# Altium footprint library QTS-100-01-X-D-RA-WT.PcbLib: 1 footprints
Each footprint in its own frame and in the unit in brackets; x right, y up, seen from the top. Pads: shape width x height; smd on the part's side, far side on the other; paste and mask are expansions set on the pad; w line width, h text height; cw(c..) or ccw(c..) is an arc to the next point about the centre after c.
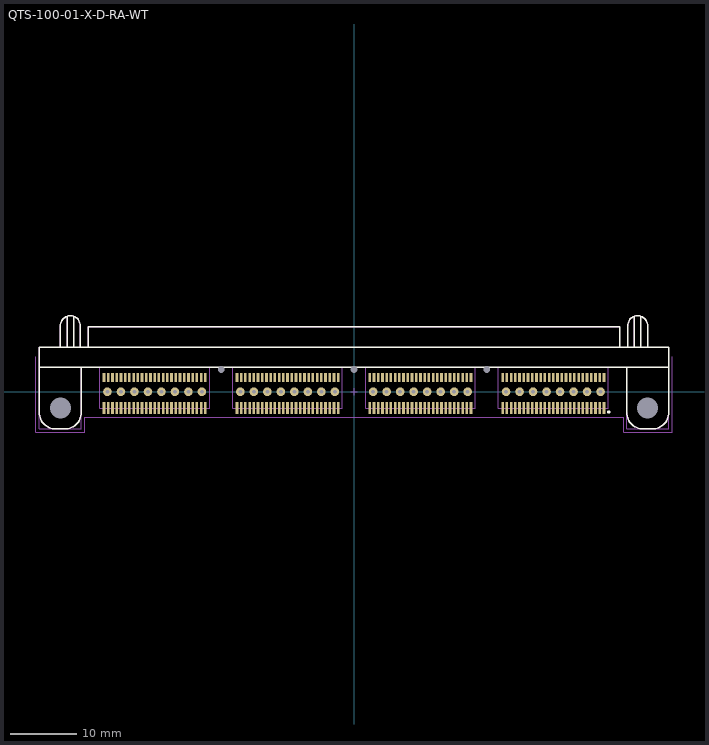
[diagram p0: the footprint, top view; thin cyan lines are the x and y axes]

## QTS-100-01-X-D-RA-WT [mm] "0.635mm pitch, 200 pin, high speed terminal strip; r/a, w/weld tabs"
height 9.42
pads (237):
  rect 0.4x1.8 smd mask+0: 1(37.624,-2.451) 3(36.989,-2.451) 5(36.354,-2.451) 7(35.719,-2.451) 9(35.084,-2.451) 11(34.449,-2.451) 13(33.814,-2.451) 15(33.179,-2.451) 17(32.544,-2.451) 19(31.909,-2.451) 21(31.274,-2.451) 23(30.639,-2.451) 25(30.004,-2.451) 27(29.369,-2.451) 29(28.734,-2.451) 31(28.099,-2.451) 33(27.464,-2.451) 35(26.829,-2.451) 37(26.194,-2.451) 39(25.559,-2.451) 41(24.924,-2.451) 43(24.289,-2.451) 45(23.654,-2.451) 47(23.019,-2.451) 49(22.384,-2.451) 51(17.621,-2.451) 53(16.986,-2.451) 55(16.351,-2.451) 57(15.716,-2.451) 59(15.081,-2.451) 61(14.446,-2.451) 63(13.811,-2.451) 65(13.176,-2.451) 67(12.541,-2.451) 69(11.906,-2.451) 71(11.271,-2.451) 73(10.636,-2.451) 75(10.001,-2.451) 77(9.366,-2.451) 79(8.731,-2.451) 81(8.096,-2.451) 83(7.461,-2.451) 85(6.826,-2.451) 87(6.191,-2.451) 89(5.556,-2.451) 91(4.921,-2.451) 93(4.286,-2.451) 95(3.651,-2.451) 97(3.016,-2.451) 99(2.381,-2.451) 101(-2.381,-2.451) 103(-3.016,-2.451) 105(-3.651,-2.451) 107(-4.286,-2.451) 109(-4.921,-2.451) 111(-5.556,-2.451) 113(-6.191,-2.451) 115(-6.826,-2.451) 117(-7.461,-2.451) 119(-8.096,-2.451) 121(-8.731,-2.451) 123(-9.366,-2.451) 125(-10.001,-2.451) 127(-10.636,-2.451) 129(-11.271,-2.451) 131(-11.906,-2.451) 133(-12.541,-2.451) 135(-13.176,-2.451) 137(-13.811,-2.451) 139(-14.446,-2.451) 141(-15.081,-2.451) 143(-15.716,-2.451) 145(-16.351,-2.451) 147(-16.986,-2.451) 149(-17.621,-2.451) 151(-22.384,-2.451) 153(-23.019,-2.451) 155(-23.654,-2.451) 157(-24.289,-2.451) 159(-24.924,-2.451) 161(-25.559,-2.451) 163(-26.194,-2.451) 165(-26.829,-2.451) 167(-27.464,-2.451) 169(-28.099,-2.451) 171(-28.734,-2.451) 173(-29.369,-2.451) 175(-30.004,-2.451) 177(-30.639,-2.451) 179(-31.274,-2.451) 181(-31.909,-2.451) 183(-32.544,-2.451) 185(-33.179,-2.451) 187(-33.814,-2.451) 189(-34.449,-2.451) 191(-35.084,-2.451) 193(-35.719,-2.451) 195(-36.354,-2.451) 197(-36.989,-2.451) 199(-37.624,-2.451)
  rect 0.4x1.4 smd mask+0: 2(37.624,2.159) 4(36.989,2.159) 6(36.354,2.159) 8(35.719,2.159) 10(35.084,2.159) 12(34.449,2.159) 14(33.814,2.159) 16(33.179,2.159) 18(32.544,2.159) 20(31.909,2.159) 22(31.274,2.159) 24(30.639,2.159) 26(30.004,2.159) 28(29.369,2.159) 30(28.734,2.159) 32(28.099,2.159) 34(27.464,2.159) 36(26.829,2.159) 38(26.194,2.159) 40(25.559,2.159) 42(24.924,2.159) 44(24.289,2.159) 46(23.654,2.159) 48(23.019,2.159) 50(22.384,2.159) 52(17.621,2.159) 54(16.986,2.159) 56(16.351,2.159) 58(15.716,2.159) 60(15.081,2.159) 62(14.446,2.159) 64(13.811,2.159) 66(13.176,2.159) 68(12.541,2.159) 70(11.906,2.159) 72(11.271,2.159) 74(10.636,2.159) 76(10.001,2.159) 78(9.366,2.159) 80(8.731,2.159) 82(8.096,2.159) 84(7.461,2.159) 86(6.826,2.159) 88(6.191,2.159) 90(5.556,2.159) 92(4.921,2.159) 94(4.286,2.159) 96(3.651,2.159) 98(3.016,2.159) 100(2.381,2.159) 102(-2.381,2.159) 104(-3.016,2.159) 106(-3.651,2.159) 108(-4.286,2.159) 110(-4.921,2.159) 112(-5.556,2.159) 114(-6.191,2.159) 116(-6.826,2.159) 118(-7.461,2.159) 120(-8.096,2.159) 122(-8.731,2.159) 124(-9.366,2.159) 126(-10.001,2.159) 128(-10.636,2.159) 130(-11.271,2.159) 132(-11.906,2.159) 134(-12.541,2.159) 136(-13.176,2.159) 138(-13.811,2.159) 140(-14.446,2.159) 142(-15.081,2.159) 144(-15.716,2.159) 146(-16.351,2.159) 148(-16.986,2.159) 150(-17.621,2.159) 152(-22.384,2.159) 154(-23.019,2.159) 156(-23.654,2.159) 158(-24.289,2.159) 160(-24.924,2.159) 162(-25.559,2.159) 164(-26.194,2.159) 166(-26.829,2.159) 168(-27.464,2.159) 170(-28.099,2.159) 172(-28.734,2.159) 174(-29.369,2.159) 176(-30.004,2.159) 178(-30.639,2.159) 180(-31.274,2.159) 182(-31.909,2.159) 184(-32.544,2.159) 186(-33.179,2.159) 188(-33.814,2.159) 190(-34.449,2.159) 192(-35.084,2.159) 194(-35.719,2.159) 196(-36.354,2.159) 198(-36.989,2.159) 200(-37.624,2.159)
  round 1.3 hole 0.6 mask+0: 201(37.116,0) 202(35.084,0) 203(33.052,0) 204(31.02,0) 205(28.988,0) 206(26.956,0) 207(24.924,0) 208(22.892,0) 209(17.113,0) 210(15.081,0) 211(13.049,0) 212(11.017,0) 213(8.985,0) 214(6.953,0) 215(4.921,0) 216(2.889,0) 217(-2.89,0) 218(-4.922,0) 219(-6.954,0) 220(-8.986,0) 221(-11.018,0) 222(-13.05,0) 223(-15.082,0) 224(-17.114,0) 225(-22.894,0) 226(-24.926,0) 227(-26.958,0) 228(-28.99,0) 229(-31.022,0) 230(-33.054,0) 231(-35.086,0) 232(-37.118,0)
  round 1 hole 3.2 unplated mask+0: 233(44.196,-2.451) 234(-44.196,-2.451)
  round 0.5 hole 1 unplated mask+0: 235(20.003,3.353) 236(0,3.353) 237(-20.003,3.353)
Top Overlay:
  circle w0.25: c38.35,-3.05 r0.125
  lines w0.2: -47.4,3.693 -47.4,-3.126 ccw(c-44.9,-3.1) -44.869,-5.6 ; -44.87,-5.6 -43.52,-5.6 ; -44.2,6.7 -44.2,9.943 cw(c-42.7,9.943) -41.2,9.943 -41.2,6.7 ; -43.519,-5.6 ccw(c-43.55,-3.1) -41.05,-3.126 ; -43.2,6.7 -43.2,11.35 ; -42.2,6.7 -42.2,11.35 ; -41.05,-3.126 -41.05,3.7 ; -40,6.7 -40,9.75 40,9.75 40,6.693 ; 41.05,-3.126 ccw(c43.55,-3.1) 43.519,-5.6 ; 41.05,-3.126 41.05,3.693 ; 41.2,6.7 41.2,9.943 cw(c42.7,9.943) 44.2,9.943 44.2,6.7 ; 42.2,6.7 42.2,11.35 ; 43.2,6.7 43.2,11.35 ; 43.52,-5.6 44.87,-5.6 ; 44.869,-5.6 ccw(c44.9,-3.1) 47.4,-3.126 47.4,3.7 ; 47.4,3.7 47.4,6.7 -47.4,6.7 -47.4,3.7 47.4,3.7
Mechanical 12:
  lines w0.001: -47.4,-5.6 -47.4,6.7 -40,6.7 -40,9.75 40,9.75 40,6.7 47.4,6.7 47.4,-5.6 41.05,-5.6 41.05,3.7 38.25,3.7 38.25,-2.5 21.75,-2.5 21.75,3.7 18.25,3.7 18.25,-2.5 1.75,-2.5 1.75,3.7 -1.75,3.7 -1.75,-2.5 -18.25,-2.5 -18.25,3.7 -21.75,3.7 -21.75,-2.5 -38.25,-2.5 -38.25,3.7 -41.05,3.7 -41.05,-5.6 -47.4,-5.6
Mechanical 13:
  lines w0.1: -47.4,3.693 -47.4,-3.126 ccw(c-44.9,-3.1) -44.869,-5.6 ; -44.87,-5.6 -43.52,-5.6 ; -44.2,6.7 -44.2,9.943 cw(c-42.7,9.943) -41.2,9.943 -41.2,6.7 ; -43.519,-5.6 ccw(c-43.55,-3.1) -41.05,-3.126 ; -43.2,6.7 -43.2,11.35 ; -42.2,6.7 -42.2,11.35 ; -41.05,-3.126 -41.05,3.7 ; -40,6.7 -40,9.75 40,9.75 40,6.693 ; -38.25,3.7 -38.25,-2.5 -21.75,-2.5 -21.75,3.7 ; -18.25,3.7 -18.25,-2.5 -1.752,-2.5 -1.752,3.7 ; 1.752,3.693 1.752,-2.5 18.25,-2.5 18.25,3.7 ; 21.75,3.7 21.75,-2.5 38.25,-2.5 38.25,3.7 ; 41.05,-3.126 ccw(c43.55,-3.1) 43.519,-5.6 ; 41.05,-3.126 41.05,3.693 ; 41.2,6.7 41.2,9.943 cw(c42.7,9.943) 44.2,9.943 44.2,6.7 ; 42.2,6.7 42.2,11.35 ; 43.2,6.7 43.2,11.35 ; 43.52,-5.6 44.87,-5.6 ; 44.869,-5.6 ccw(c44.9,-3.1) 47.4,-3.126 47.4,3.7 ; 47.4,3.7 47.4,6.7 -47.4,6.7 -47.4,3.7 47.4,3.7
  text ".Designator" at 0.127,-0.127 h1.52
Mechanical 15:
  lines w0.05: -47.9,5.296 -47.9,-6.1 -40.55,-6.1 -40.55,-3.85 40.6,-3.85 40.6,-6.1 47.9,-6.1 47.9,5.296 ; -0.5,0 0.5,0 ; 0,-0.5 0,0.5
